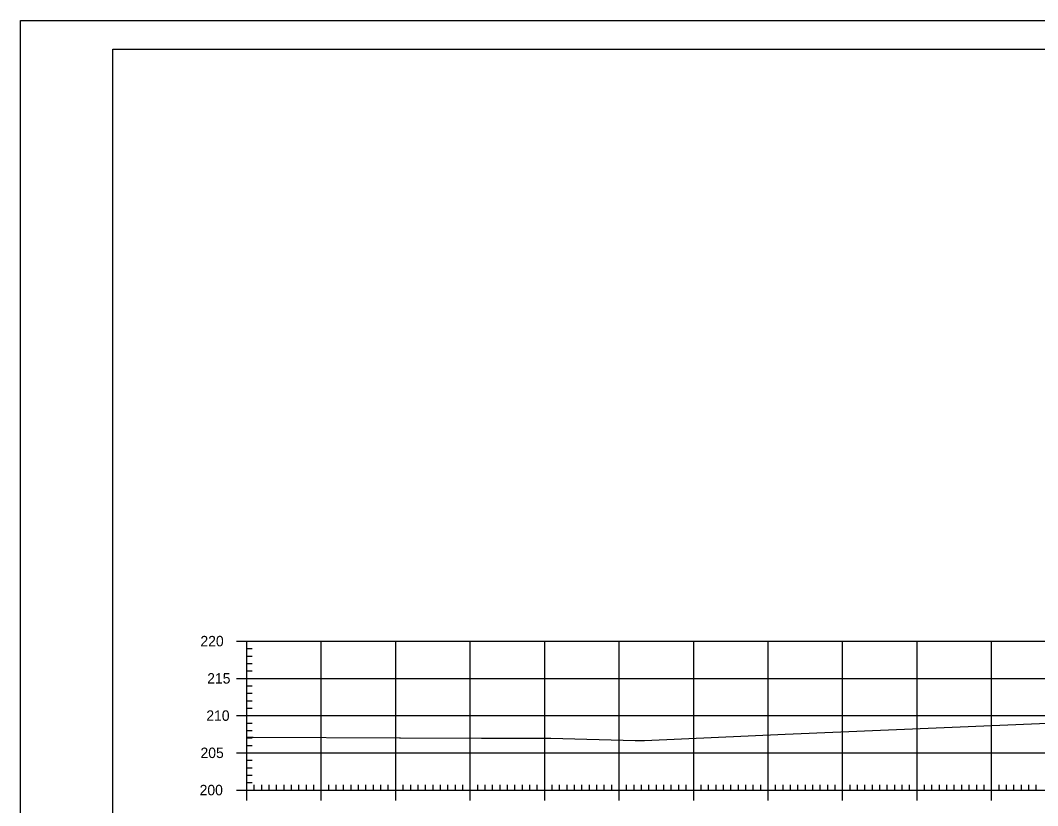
# Model space of a CAD drawing. Extents: x 1312042 to 1371461, y 379929 to 1834241.
# Drawn here: x 1371127.9 to 1371264.5, y 380250.2 to 380355.6 of the extents above; entities that cross this region are included whole.
import ezdxf

# ---------------------------------------------------------------- set-up
doc = ezdxf.new("R2010")
doc.units = 0
for name, color, linetype in [('R_Axis', 7, 'Continuous'), ('R_Axis Annot', 7, 'Continuous'), ('R_Border', 7, 'Continuous'), ('R_Exist Surface', 7, 'Continuous'), ('R_Grid', 7, 'Continuous'), ('R_No Plot', 7, 'Continuous')]:
    doc.layers.add(name, color=color, linetype=linetype)

msp = doc.modelspace()

# ---------------------------------------------------------------- linework, layer by layer
at = {"layer": 'R_Axis'}
for p, q in [((1371156.88, 380272.25), (1371159.68, 380272.25)), ((1371158.28, 380252.25), (1371158.28, 380272.25)), ((1371158.28, 380271.25), (1371158.98, 380271.25)), ((1371158.28, 380270.25), (1371158.98, 380270.25)), ((1371158.28, 380269.25), (1371158.98, 380269.25)), ((1371156.88, 380267.25), (1371159.68, 380267.25)), ((1371158.28, 380268.25), (1371158.98, 380268.25)), ((1371158.28, 380266.25), (1371158.98, 380266.25)), ((1371158.28, 380265.25), (1371158.98, 380265.25)), ((1371158.28, 380264.25), (1371158.98, 380264.25)), ((1371158.28, 380263.25), (1371158.98, 380263.25)), ((1371156.88, 380262.25), (1371159.68, 380262.25)), ((1371158.28, 380261.25), (1371158.98, 380261.25)), ((1371158.28, 380260.25), (1371158.98, 380260.25)), ((1371158.28, 380259.25), (1371158.98, 380259.25)), ((1371158.28, 380258.25), (1371158.98, 380258.25)), ((1371156.88, 380257.25), (1371159.68, 380257.25)), ((1371158.28, 380256.25), (1371158.98, 380256.25)), ((1371158.28, 380255.25), (1371158.98, 380255.25)), ((1371158.28, 380254.25), (1371158.98, 380254.25)), ((1371158.28, 380250.85), (1371158.28, 380253.65)), ((1371168.28, 380250.85), (1371168.28, 380253.65)), ((1371178.28, 380250.85), (1371178.28, 380253.65)), ((1371188.28, 380250.85), (1371188.28, 380253.65)), ((1371198.28, 380250.85), (1371198.28, 380253.65)), ((1371208.28, 380250.85), (1371208.28, 380253.65)), ((1371218.28, 380250.85), (1371218.28, 380253.65)), ((1371228.28, 380250.85), (1371228.28, 380253.65)), ((1371238.28, 380250.85), (1371238.28, 380253.65)), ((1371248.28, 380250.85), (1371248.28, 380253.65)), ((1371258.28, 380250.85), (1371258.28, 380253.65)), ((1371156.88, 380252.25), (1371159.68, 380252.25)), ((1371158.28, 380253.25), (1371158.98, 380253.25)), ((1371158.28, 380252.25), (1371438.28, 380252.25)), ((1371159.28, 380252.25), (1371159.28, 380252.95)), ((1371160.28, 380252.25), (1371160.28, 380252.95)), ((1371161.28, 380252.25), (1371161.28, 380252.95)), ((1371162.28, 380252.25), (1371162.28, 380252.95)), ((1371163.28, 380252.25), (1371163.28, 380252.95)), ((1371164.28, 380252.25), (1371164.28, 380252.95)), ((1371165.28, 380252.25), (1371165.28, 380252.95)), ((1371166.28, 380252.25), (1371166.28, 380252.95)), ((1371167.28, 380252.25), (1371167.28, 380252.95)), ((1371169.28, 380252.25), (1371169.28, 380252.95)), ((1371170.28, 380252.25), (1371170.28, 380252.95)), ((1371171.28, 380252.25), (1371171.28, 380252.95)), ((1371172.28, 380252.25), (1371172.28, 380252.95)), ((1371173.28, 380252.25), (1371173.28, 380252.95)), ((1371174.28, 380252.25), (1371174.28, 380252.95)), ((1371175.28, 380252.25), (1371175.28, 380252.95)), ((1371176.28, 380252.25), (1371176.28, 380252.95)), ((1371177.28, 380252.25), (1371177.28, 380252.95)), ((1371179.28, 380252.25), (1371179.28, 380252.95)), ((1371180.28, 380252.25), (1371180.28, 380252.95)), ((1371181.28, 380252.25), (1371181.28, 380252.95)), ((1371182.28, 380252.25), (1371182.28, 380252.95)), ((1371183.28, 380252.25), (1371183.28, 380252.95)), ((1371184.28, 380252.25), (1371184.28, 380252.95)), ((1371185.28, 380252.25), (1371185.28, 380252.95)), ((1371186.28, 380252.25), (1371186.28, 380252.95)), ((1371187.28, 380252.25), (1371187.28, 380252.95)), ((1371189.28, 380252.25), (1371189.28, 380252.95)), ((1371190.28, 380252.25), (1371190.28, 380252.95)), ((1371191.28, 380252.25), (1371191.28, 380252.95)), ((1371192.28, 380252.25), (1371192.28, 380252.95)), ((1371193.28, 380252.25), (1371193.28, 380252.95)), ((1371194.28, 380252.25), (1371194.28, 380252.95)), ((1371195.28, 380252.25), (1371195.28, 380252.95)), ((1371196.28, 380252.25), (1371196.28, 380252.95)), ((1371197.28, 380252.25), (1371197.28, 380252.95)), ((1371199.28, 380252.25), (1371199.28, 380252.95)), ((1371200.28, 380252.25), (1371200.28, 380252.95)), ((1371201.28, 380252.25), (1371201.28, 380252.95)), ((1371202.28, 380252.25), (1371202.28, 380252.95)), ((1371203.28, 380252.25), (1371203.28, 380252.95)), ((1371204.28, 380252.25), (1371204.28, 380252.95)), ((1371205.28, 380252.25), (1371205.28, 380252.95)), ((1371206.28, 380252.25), (1371206.28, 380252.95)), ((1371207.28, 380252.25), (1371207.28, 380252.95)), ((1371209.28, 380252.25), (1371209.28, 380252.95)), ((1371210.28, 380252.25), (1371210.28, 380252.95)), ((1371211.28, 380252.25), (1371211.28, 380252.95)), ((1371212.28, 380252.25), (1371212.28, 380252.95)), ((1371213.28, 380252.25), (1371213.28, 380252.95)), ((1371214.28, 380252.25), (1371214.28, 380252.95)), ((1371215.28, 380252.25), (1371215.28, 380252.95)), ((1371216.28, 380252.25), (1371216.28, 380252.95)), ((1371217.28, 380252.25), (1371217.28, 380252.95)), ((1371219.28, 380252.25), (1371219.28, 380252.95)), ((1371220.28, 380252.25), (1371220.28, 380252.95)), ((1371221.28, 380252.25), (1371221.28, 380252.95)), ((1371222.28, 380252.25), (1371222.28, 380252.95)), ((1371223.28, 380252.25), (1371223.28, 380252.95)), ((1371224.28, 380252.25), (1371224.28, 380252.95)), ((1371225.28, 380252.25), (1371225.28, 380252.95)), ((1371226.28, 380252.25), (1371226.28, 380252.95)), ((1371227.28, 380252.25), (1371227.28, 380252.95)), ((1371229.28, 380252.25), (1371229.28, 380252.95)), ((1371230.28, 380252.25), (1371230.28, 380252.95)), ((1371231.28, 380252.25), (1371231.28, 380252.95)), ((1371232.28, 380252.25), (1371232.28, 380252.95)), ((1371233.28, 380252.25), (1371233.28, 380252.95)), ((1371234.28, 380252.25), (1371234.28, 380252.95)), ((1371235.28, 380252.25), (1371235.28, 380252.95)), ((1371236.28, 380252.25), (1371236.28, 380252.95)), ((1371237.28, 380252.25), (1371237.28, 380252.95)), ((1371239.28, 380252.25), (1371239.28, 380252.95)), ((1371240.28, 380252.25), (1371240.28, 380252.95)), ((1371241.28, 380252.25), (1371241.28, 380252.95)), ((1371242.28, 380252.25), (1371242.28, 380252.95)), ((1371243.28, 380252.25), (1371243.28, 380252.95)), ((1371244.28, 380252.25), (1371244.28, 380252.95)), ((1371245.28, 380252.25), (1371245.28, 380252.95)), ((1371246.28, 380252.25), (1371246.28, 380252.95)), ((1371247.28, 380252.25), (1371247.28, 380252.95)), ((1371249.28, 380252.25), (1371249.28, 380252.95)), ((1371250.28, 380252.25), (1371250.28, 380252.95)), ((1371251.28, 380252.25), (1371251.28, 380252.95)), ((1371252.28, 380252.25), (1371252.28, 380252.95)), ((1371253.28, 380252.25), (1371253.28, 380252.95)), ((1371254.28, 380252.25), (1371254.28, 380252.95)), ((1371255.28, 380252.25), (1371255.28, 380252.95)), ((1371256.28, 380252.25), (1371256.28, 380252.95)), ((1371257.28, 380252.25), (1371257.28, 380252.95)), ((1371259.28, 380252.25), (1371259.28, 380252.95)), ((1371260.28, 380252.25), (1371260.28, 380252.95)), ((1371261.28, 380252.25), (1371261.28, 380252.95)), ((1371262.28, 380252.25), (1371262.28, 380252.95)), ((1371263.28, 380252.25), (1371263.28, 380252.95)), ((1371264.28, 380252.25), (1371264.28, 380252.95))]:
    msp.add_line(p, q, dxfattribs=at)
at = {"layer": 'R_Border'}
for p, q in [((1371140.28, 380351.71), (1371456.46, 380351.71)), ((1371140.28, 380146.25), (1371140.28, 380351.71))]:
    msp.add_line(p, q, dxfattribs=at)
at = {"layer": 'R_Exist Surface'}
msp.add_lwpolyline([(1371158.28, 380259.35), (1371158.77, 380259.35), (1371159.15, 380259.35), (1371178.77, 380259.27), (1371178.91, 380259.27), (1371189.81, 380259.23), (1371199.11, 380259.2), (1371210.43, 380258.89), (1371211.66, 380258.91), (1371230.56, 380259.75), (1371265.8, 380261.22)], dxfattribs=at)
at = {"layer": 'R_Grid'}
for p, q in [((1371158.28, 380272.25), (1371438.28, 380272.25)), ((1371158.28, 380252.25), (1371158.28, 380272.25)), ((1371168.28, 380252.25), (1371168.28, 380272.25)), ((1371178.28, 380252.25), (1371178.28, 380272.25)), ((1371188.28, 380252.25), (1371188.28, 380272.25)), ((1371198.28, 380252.25), (1371198.28, 380272.25)), ((1371208.28, 380252.25), (1371208.28, 380272.25)), ((1371218.28, 380252.25), (1371218.28, 380272.25)), ((1371228.28, 380252.25), (1371228.28, 380272.25)), ((1371238.28, 380252.25), (1371238.28, 380272.25)), ((1371248.28, 380252.25), (1371248.28, 380272.25)), ((1371258.28, 380252.25), (1371258.28, 380272.25)), ((1371158.28, 380267.25), (1371438.28, 380267.25)), ((1371158.28, 380262.25), (1371438.28, 380262.25)), ((1371158.28, 380257.25), (1371438.28, 380257.25)), ((1371158.28, 380252.25), (1371438.28, 380252.25))]:
    msp.add_line(p, q, dxfattribs=at)
at = {"layer": 'R_No Plot'}
msp.add_line((1371127.88, 380355.6), (1371461.21, 380355.6), dxfattribs=at)
for points in [[(1371127.87, 380355.6), (1371461.21, 380355.6), (1371461.21, 380142.26), (1371127.87, 380142.26)], [(1371374.2, 380351.71), (1371374.2, 380341.83), (1371409.93, 380341.83), (1371409.93, 380338.91), (1371433.13, 380338.91), (1371433.13, 380314.57), (1371456.46, 380314.57), (1371456.46, 380146.25), (1371140.28, 380146.25), (1371140.28, 380351.71)]]:
    msp.add_lwpolyline(points, close=True, dxfattribs=at)

# ---------------------------------------------------------------- texts
at = {"layer": 'R_Axis Annot'}
for s, p in [('220', (1371152.05, 380271.55)), ('215', (1371152.96, 380266.55)), ('210', (1371152.84, 380261.55)), ('205', (1371152.06, 380256.55)), ('200', (1371151.94, 380251.55))]:
    msp.add_text(s, height=1.4, dxfattribs=at).set_placement(p)

doc.saveas('drawing.dxf')
